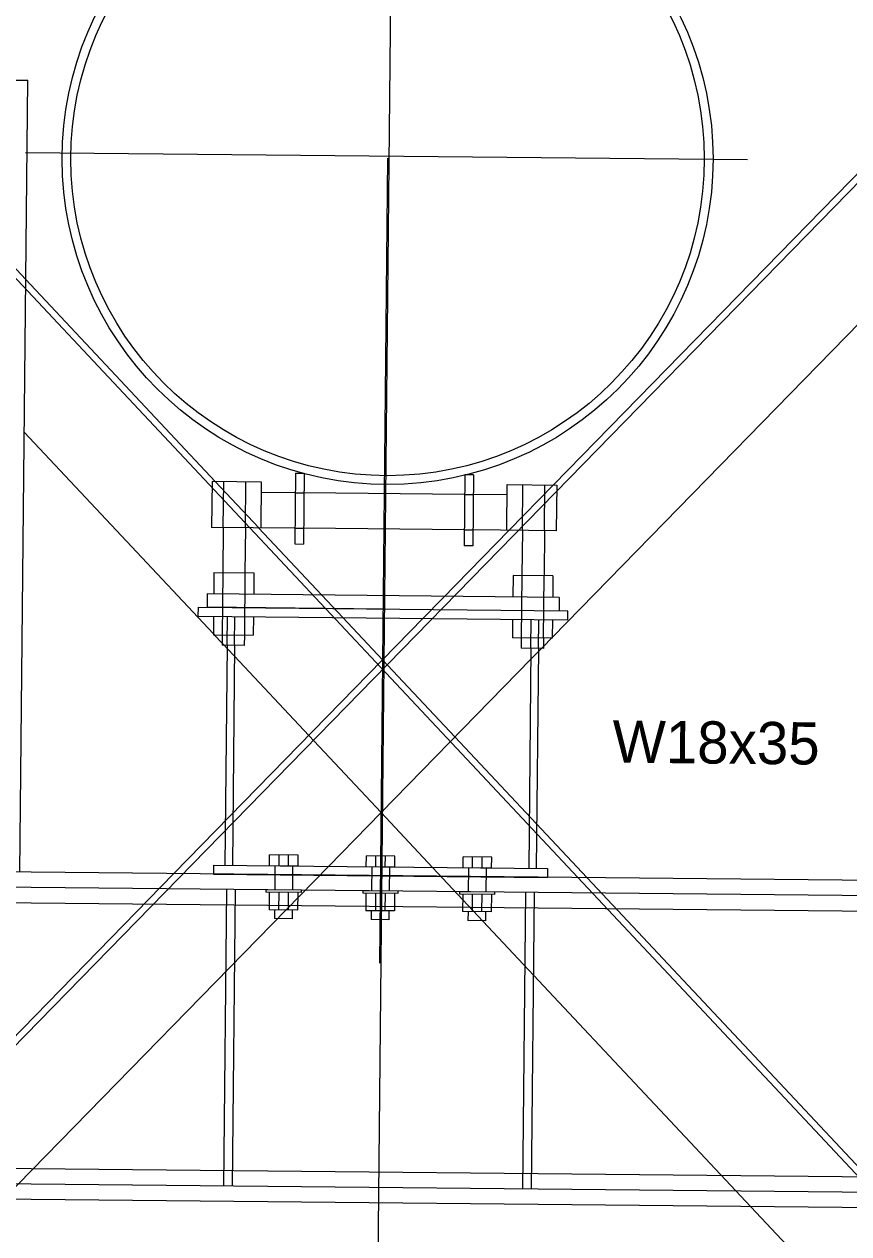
# Model space of a CAD drawing. Extents: x 632312 to 632885, y 378199 to 378534.
# Drawn here: x 632532.33 to 632536.24, y 378443.74 to 378449.47 of the extents above; entities that cross this region are included whole.
import ezdxf

# ---------------------------------------------------------------- set-up
doc = ezdxf.new("R2010")
doc.units = 0
for name, color, linetype in [('B_Boring', 7, 'Continuous'), ('R_Proposed Const Limits Cut', 7, 'Continuous'), ('R_Road Edge of Shoulder', 7, 'Continuous'), ('SHT_Dimensions', 7, 'Continuous')]:
    doc.layers.add(name, color=color, linetype=linetype)

msp = doc.modelspace()

# ---------------------------------------------------------------- linework, layer by layer
at = {"layer": 'B_Boring'}
for p, q in [((632532.0157, 378449.2034), (632532.349, 378449.2001)), ((632532.3117, 378445.4503), (632532.349, 378449.2001)), ((632533.2222, 378447.3), (632533.2201, 378447.0832)), ((632533.4564, 378447.2976), (632533.2222, 378447.3)), ((632533.4542, 378447.0808), (632533.4564, 378447.2976)), ((632533.6176, 378447.3401), (632533.6143, 378447.0043)), ((632533.6176, 378447.3401), (632533.6587, 378447.3397)), ((632533.6587, 378447.3397), (632533.6553, 378447.0039)), ((632534.4192, 378447.3322), (632534.4158, 378446.9963)), ((632534.4602, 378447.3317), (632534.4192, 378447.3322)), ((632534.4602, 378447.3317), (632534.4569, 378446.9959)), ((632533.6167, 378447.2472), (632533.4559, 378447.2488)), ((632534.4182, 378447.2393), (632533.6577, 378447.2468)), ((632534.6201, 378447.2373), (632534.4593, 378447.2388)), ((632534.6184, 378447.0693), (632534.6206, 378447.286)), ((632534.6206, 378447.286), (632534.8547, 378447.2837)), ((632534.8547, 378447.2837), (632534.8525, 378447.0669)), ((632533.615, 378447.0792), (632533.2201, 378447.0832)), ((632533.2756, 378447.0826), (632533.2735, 378446.8691)), ((632533.3804, 378447.0816), (632533.3783, 378446.8681)), ((632534.4166, 378447.0713), (632533.6561, 378447.0788)), ((632534.8525, 378447.0669), (632534.4576, 378447.0709)), ((632534.6922, 378447.0685), (632534.6901, 378446.855)), ((632534.797, 378447.0675), (632534.7949, 378446.854)), ((632533.6143, 378447.0043), (632533.6553, 378447.0039)), ((632534.4569, 378446.9959), (632534.4158, 378446.9963)), ((632533.2313, 378446.8695), (632533.2303, 378446.7674)), ((632533.2313, 378446.8695), (632533.4205, 378446.8677)), ((632533.4205, 378446.8677), (632533.4195, 378446.7655)), ((632534.6479, 378446.8554), (632534.6469, 378446.7533)), ((632534.8371, 378446.8536), (632534.6479, 378446.8554)), ((632534.8371, 378446.8536), (632534.8361, 378446.7514)), ((632533.1999, 378446.7677), (632533.1993, 378446.7045)), ((632534.8665, 378446.7511), (632533.1999, 378446.7677)), ((632534.8665, 378446.7511), (632534.8658, 378446.6879)), ((632533.1572, 378446.6633), (632533.1576, 378446.705)), ((632533.1576, 378446.7049), (632534.9075, 378446.6875)), ((632534.9071, 378446.6459), (632534.9075, 378446.6876)), ((632533.1572, 378446.6633), (632534.9071, 378446.6459)), ((632533.2293, 378446.6625), (632533.2284, 378446.5745)), ((632533.4184, 378446.6607), (632533.4176, 378446.5726)), ((632534.6459, 378446.6485), (632534.645, 378446.5604)), ((632534.835, 378446.6466), (632534.8341, 378446.5585)), ((632533.2284, 378446.5745), (632533.4176, 378446.5726)), ((632533.2706, 378446.5741), (632533.2701, 378446.5251)), ((632533.3754, 378446.573), (632533.3749, 378446.524)), ((632534.8341, 378446.5585), (632534.645, 378446.5604)), ((632534.6872, 378446.56), (632534.6867, 378446.511)), ((632534.792, 378446.559), (632534.7915, 378446.5099)), ((632533.3749, 378446.524), (632533.2701, 378446.5251)), ((632533.2933, 378446.5248), (632533.2829, 378445.4823)), ((632533.3287, 378446.5245), (632533.3184, 378445.482)), ((632534.7915, 378446.5099), (632534.6867, 378446.511)), ((632534.7328, 378446.5105), (632534.7225, 378445.468)), ((632534.7682, 378446.5102), (632534.7579, 378445.4677)), ((632533.4944, 378445.4802), (632533.4949, 378445.5323)), ((632533.6303, 378445.531), (632533.4949, 378445.5323)), ((632533.5395, 378445.4798), (632533.54, 378445.5319)), ((632533.5847, 378445.4793), (632533.5852, 378445.5314)), ((632533.6298, 378445.4789), (632533.6303, 378445.531)), ((632533.9527, 378445.4757), (632533.9532, 378445.5278)), ((632534.0886, 378445.5264), (632533.9532, 378445.5278)), ((632533.9978, 378445.4752), (632533.9984, 378445.5273)), ((632534.043, 378445.4748), (632534.0435, 378445.5269)), ((632534.0881, 378445.4743), (632534.0886, 378445.5264)), ((632534.411, 378445.4711), (632534.4115, 378445.5232)), ((632534.5469, 378445.5219), (632534.4115, 378445.5232)), ((632534.4562, 378445.4707), (632534.4567, 378445.5227)), ((632534.5013, 378445.4702), (632534.5018, 378445.5223)), ((632534.5464, 378445.4698), (632534.5469, 378445.5219)), ((632539.5197, 378445.3787), (632528.5203, 378445.488)), ((632533.2288, 378445.4829), (632533.2284, 378445.4412)), ((632533.2288, 378445.4829), (632534.812, 378445.4671)), ((632533.6298, 378445.4789), (632533.4944, 378445.4802)), ((632533.5204, 378445.48), (632533.5193, 378445.3658)), ((632533.6038, 378445.4791), (632533.6026, 378445.365)), ((632534.0881, 378445.4743), (632533.9527, 378445.4757)), ((632533.9787, 378445.4754), (632533.9776, 378445.3613)), ((632534.0621, 378445.4746), (632534.0609, 378445.3604)), ((632534.5464, 378445.4698), (632534.411, 378445.4711)), ((632534.4371, 378445.4709), (632534.4359, 378445.3567)), ((632534.5204, 378445.47), (632534.5193, 378445.3559)), ((632534.812, 378445.4671), (632534.8116, 378445.4254)), ((632539.519, 378445.3062), (632528.5195, 378445.4155)), ((632533.2284, 378445.4412), (632534.8116, 378445.4255)), ((632533.2901, 378445.3681), (632533.2762, 378443.9632)), ((632533.3318, 378445.3677), (632533.3178, 378443.9627)), ((632533.4776, 378445.3662), (632533.4775, 378445.3558)), ((632533.6442, 378445.3542), (632533.4775, 378445.3558)), ((632533.6443, 378445.3646), (632533.4776, 378445.3662)), ((632533.4932, 378445.3557), (632533.4923, 378445.2723)), ((632533.5383, 378445.3552), (632533.5375, 378445.2719)), ((632533.5834, 378445.3548), (632533.5826, 378445.2714)), ((632533.6286, 378445.3543), (632533.6277, 378445.271)), ((632533.6443, 378445.3646), (632533.6442, 378445.3542)), ((632533.9359, 378445.3617), (632533.9358, 378445.3513)), ((632534.1025, 378445.3496), (632533.9358, 378445.3513)), ((632534.1026, 378445.36), (632533.9359, 378445.3617)), ((632533.9515, 378445.3511), (632533.9506, 378445.2678)), ((632533.9966, 378445.3506), (632533.9958, 378445.2673)), ((632534.0417, 378445.3502), (632534.0409, 378445.2669)), ((632534.0869, 378445.3498), (632534.086, 378445.2664)), ((632534.1026, 378445.36), (632534.1025, 378445.3496)), ((632534.3943, 378445.3571), (632534.3942, 378445.3467)), ((632534.5609, 378445.3555), (632534.3943, 378445.3571)), ((632534.5609, 378445.3555), (632534.5608, 378445.345)), ((632534.7067, 378445.354), (632534.6928, 378443.9491)), ((632534.7484, 378445.3536), (632534.7344, 378443.9487)), ((632534.5608, 378445.345), (632534.3942, 378445.3467)), ((632534.4098, 378445.3465), (632534.409, 378445.2632)), ((632534.4549, 378445.3461), (632534.4541, 378445.2628)), ((632534.5001, 378445.3456), (632534.4992, 378445.2623)), ((632534.5452, 378445.3452), (632534.5444, 378445.2619)), ((632533.6277, 378445.271), (632533.4923, 378445.2723)), ((632533.5184, 378445.2721), (632533.518, 378445.2304)), ((632533.6017, 378445.2712), (632533.6013, 378445.2296)), ((632534.086, 378445.2664), (632533.9506, 378445.2678)), ((632533.9767, 378445.2675), (632533.9763, 378445.2258)), ((632534.06, 378445.2667), (632534.0596, 378445.225)), ((632534.5444, 378445.2619), (632534.409, 378445.2632)), ((632534.435, 378445.263), (632534.4346, 378445.2213)), ((632534.5183, 378445.2621), (632534.5179, 378445.2205)), ((632533.6013, 378445.2296), (632533.518, 378445.2304)), ((632534.0596, 378445.225), (632533.9763, 378445.2258)), ((632534.5179, 378445.2205), (632534.4346, 378445.2213)), ((632539.505, 378443.9012), (632528.5056, 378444.0106)), ((632539.5043, 378443.8287), (632528.5049, 378443.9381))]:
    msp.add_line(p, q, dxfattribs=at)
for points in [[(632534.8342, 378446.563), (632538.6116, 378450.4305), (632538.2539, 378450.7799), (632534.8393, 378447.2839)], [(632532.3396, 378448.2565), (632533.2376, 378447.2998)], [(632533.2284, 378446.579), (632532.3325, 378447.5336)], [(632533.443, 378447.0809), (632533.7421, 378446.7623)], [(632534.6296, 378447.0691), (632534.3142, 378446.7462)], [(632534.2229, 378446.6527), (632534.0302, 378446.4554), (632533.0415, 378445.4431)], [(632533.8414, 378446.6565), (632534.0302, 378446.4554)], [(632533.2702, 378446.5345), (632533.2326, 378446.5745)], [(632534.7916, 378446.5194), (632534.8299, 378446.5586)], [(632533.2932, 378446.51), (632533.2791, 378446.525)], [(632534.7681, 378446.4953), (632534.7825, 378446.51)], [(632533.6805, 378446.0973), (632533.3282, 378446.4726)], [(632533.7739, 378445.4775), (632534.023, 378445.7324), (632534.7323, 378446.4587)], [(632534.3727, 378446.0905), (632534.9985, 378445.4236)], [(632534.2669, 378445.4726), (632534.023, 378445.7324)], [(632538.1599, 378441.3248), (632535.7749, 378443.8658)]]:
    msp.add_lwpolyline(points, dxfattribs=at)
for radius in [1.5417, 1.5]:
    msp.add_circle((632534.0537, 378448.8279), radius, dxfattribs=at)
at = {"layer": 'R_Proposed Const Limits Cut'}
for p, q in [((632529.8705, 378450.8416), (632538.5017, 378441.6455)), ((632538.2762, 378450.7581), (632529.4639, 378441.7354)), ((632532.0098, 378448.608), (632532.3396, 378448.2565)), ((632533.4442, 378447.0809), (632533.2375, 378447.2998)), ((632533.2756, 378447.0826), (632533.2778, 378447.2994)), ((632533.3804, 378447.0816), (632533.3826, 378447.2984)), ((632533.6167, 378447.2472), (632533.6577, 378447.2468)), ((632534.4182, 378447.2393), (632534.4593, 378447.2388)), ((632534.6296, 378447.0691), (632534.8393, 378447.2839)), ((632534.6922, 378447.0685), (632534.6944, 378447.2853)), ((632534.797, 378447.0675), (632534.7992, 378447.2843)), ((632533.615, 378447.0792), (632533.6561, 378447.0788)), ((632534.4166, 378447.0713), (632534.4576, 378447.0709)), ((632533.2735, 378446.8691), (632533.2706, 378446.5741)), ((632533.3783, 378446.8681), (632533.3754, 378446.573)), ((632534.6901, 378446.855), (632534.6872, 378446.56)), ((632534.792, 378446.559), (632534.7949, 378446.854)), ((632533.8414, 378446.6565), (632533.7421, 378446.7623)), ((632534.2229, 378446.6527), (632534.3142, 378446.7462)), ((632533.2933, 378446.5248), (632533.2947, 378446.6619)), ((632533.3287, 378446.5245), (632533.3301, 378446.6615)), ((632534.7328, 378446.5105), (632534.7342, 378446.6476)), ((632534.7682, 378446.5102), (632534.7696, 378446.6472)), ((632533.2284, 378446.579), (632533.2326, 378446.5745)), ((632534.8299, 378446.5586), (632534.8342, 378446.563)), ((632533.2702, 378446.5345), (632533.2791, 378446.525)), ((632533.2932, 378446.51), (632533.3282, 378446.4726)), ((632534.7323, 378446.4587), (632534.7681, 378446.4953)), ((632534.7825, 378446.51), (632534.7916, 378446.5194)), ((632534.3727, 378446.0905), (632534.0302, 378446.4554)), ((632533.6805, 378446.0973), (632534.023, 378445.7324)), ((632532.2343, 378443.901), (632533.7739, 378445.4775)), ((632534.2669, 378445.4726), (632535.7749, 378443.8658)), ((632533.0415, 378445.4431), (632531.5421, 378443.9079)), ((632534.9985, 378445.4236), (632536.4671, 378443.8589)), ((632539.5183, 378445.2328), (632528.5188, 378445.3422)), ((632539.5058, 378443.9746), (632528.5063, 378444.0839))]:
    msp.add_line(p, q, dxfattribs=at)
at = {"layer": 'R_Road Edge of Shoulder'}
msp.add_line((632533.9309, 378435.7656), (632534.2608, 378468.9425), dxfattribs=at)
at = {"layer": 'SHT_Dimensions'}
for p, q in [((632532.3382, 378448.859), (632535.7587, 378448.825)), ((632534.0538, 378448.8315), (632534.0159, 378445.0199)), ((632534.0326, 378446.6962), (632533.1993, 378446.7045))]:
    msp.add_line(p, q, dxfattribs=at)

# ---------------------------------------------------------------- texts
msp.add_text('W18x35', height=0.2, rotation=359.4304, dxfattribs=at).set_placement((632535.1185, 378445.9692))

doc.saveas('drawing.dxf')
